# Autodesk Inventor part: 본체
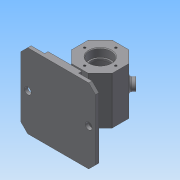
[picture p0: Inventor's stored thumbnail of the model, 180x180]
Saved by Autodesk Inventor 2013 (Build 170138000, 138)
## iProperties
Created: 2018-06
Part Number: 본체
Material: 일반
Document SubType Name: Modeling
Designer: Administrator
Density: 1 g/cm^3
Author: Administrator
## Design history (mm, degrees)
sketch "스케치1"
  geometry: L1 (-55, -62)-(55, -62); L2 (55, -62)-(55, -57); L3 (55, -57)-(25, -57); L4 (25, -57)-(25, -52); L5 (25, -52)-(-25, -52); L6 (-25, -52)-(-25, -57); L7 (-25, -57)-(-55, -57); L8 (-55, -57)-(-55, -62); L9 (0, 0)-(12.426, 30); L10 (0, 0)-(-12.426, 30); L11 (0, 0)-(0, 43.972); L12 (0, 0)-(-21.128, 0); L13 (12.426, 30)-(-12.426, 30); C1 r 30 at (0, 0); 1 further point
  constraints: 26 end point, 7 parallel, 2 perpendicular, 1 centre point, 1 coincident, 1 horizontal
  dimensions: "d0" = 60 diameter of C1; "d1" = 22.5 deg angle of L9 L11; "d3" = 22.5 deg angle of L11 L10; "d6" = 30 distance between parallel lines of L13 L12; "d7" = 92 distance from line of L1.start L13; "d8" = 110 distance of L1.start L1.end; "d9" = 55 horizontal distance of point (0, 0) L1.start; "d10" = 10 vertical distance of L4.end L1.end; "d11" = 5 distance of L3.end L4.end; "d12" = 5 distance of L5.end L6.end; "d13" = 30 distance between parallel lines of L6 L8; "d14" = 30 distance between parallel lines of L2 L4
extrude "돌출1" new body sketch "스케치1" stored distance "d15" = 110; taper "d16" = 0 deg
extrude "돌출2" join sketch "스케치1" stored distance "d17" = 70; taper "d18" = 0 deg
sketch "스케치2"
  geometry: L1 (0, 110)-(50, 110) reference; L2 (20, 74)-(20, 36); L3 (30, 36)-(30, 74); L4 (25, 55)-(6.101, 55); A1 r 5 centre (25, 36) between (20, 36) and (30, 36); A2 r 5 centre (25, 74) between (30, 74) and (20, 74)
  constraints: 6 end point, 4 point on circle, 4 tangent, 2 centre point, 2 perpendicular, 1 parallel, 1 vertical alignment
  dimensions: "d24" = 10 distance between parallel lines of L3 L2; "d26" = 38 distance of A1.centre A2.centre; "d27" = 24 dimension on A2 L4
extrude "돌출3" join sketch "스케치2" stored distance "d28" = 70; taper "d29" = 0 deg
sketch "스케치3"
  geometry: L1 (30, 110)-(30, 0) reference; C1 r 5 at (20, 55); 1 further point
  constraints: 1 centre point, 1 horizontal alignment
  dimensions: "d30" = 10 diameter of C1; "d31" = 10 distance from line of C1.centre L1
extrude "돌출4" cut sketch "스케치3" distance "d32" = 70; taper "d33" = 0 deg
sketch "스케치5"
  geometry: 1 further point
hole "구멍1" sketch "스케치5" at (0, 0) diameter "d34" = 28; stored, may be unused: countersink angle "d38" = 90 deg, drill point angle "d40" = 0 deg; dims "d35" = 6, "d36" = 32, "d37" = 12, "d39" = 15
sketch "스케치6"
  geometry: 1 further point
hole "구멍2" sketch "스케치6" at (0, 0) diameter "d41" = 28; stored, may be unused: countersink angle "d45" = 90 deg, drill point angle "d47" = 0 deg; dims "d42" = 6, "d43" = 32, "d44" = 12, "d46" = 15
hole "구멍3" diameter "d50" = 50; stored, may be unused: countersink angle "d54" = 90 deg, drill point angle "d56" = 0 deg; dims "d48" = 10, "d49" = 10, "d51" = 6, "d52" = 32, "d53" = 12, "d55" = 40
sketch "스케치7"
  geometry: C1 r 16 at (0, 0) reference; 1 further point
  constraints: 1 vertical alignment
  dimensions: "d57" = 23 distance of point (0, 23) C1.centre
hole "구멍4" sketch "스케치7" at (0, 23) diameter "d58" = 3.242; stored, may be unused: countersink angle "d62" = 90 deg, drill point angle "d64" = 118 deg; dims "d59" = 8, "d60" = 32, "d61" = 12, "d63" = 10
sketch "스케치8"
  geometry: L1 (24.853, 0)-(0, 0) reference; L2 (-17.574, 70)-(-17.574, 0) reference; 2 further points
  constraints: 1 other
  dimensions: "d68" = 30 distance from line of L2 point (12.426, 35); "d69" = 35 distance from line of L1 point (12.426, 35)
feature "엠보싱1" sketch "스케치8" dims "d70" = 0.5, "d71" = 0
node "작업 평면1"
sketch "스케치9"
  geometry: L1 (50, -62)-(50, -57) reference; L2 (50, -57)-(55, -57) reference; L3 (55, -57)-(55, -62) reference; L4 (55, -62)-(50, -62) reference; L5 (5, -30)-(5, -52) reference; L6 (5, -52)-(25, -52) reference; L7 (25, -52)-(25, -57) reference; L8 (25, -57)-(40, -57) reference; L9 (40, -57)-(40, -62) reference; L10 (40, -62)-(-40, -62) reference; L11 (-40, -62)-(-40, -57) reference; L12 (-40, -57)-(-25, -57) reference; L13 (-25, -57)-(-25, -52) reference; L14 (-25, -52)-(-5, -52) reference; L15 (-5, -52)-(-5, -30) reference; L16 (-5, -30)-(-12.426, -30) reference; L17 (-12.426, -30)-(-30, -12.426) reference; L18 (-30, -12.426)-(-30, 12.426) reference; L19 (-30, 12.426)-(-12.426, 30) reference; L20 (-12.426, 30)-(-2.862, 30) reference; L21 (-2.862, 30)-(-2.862, 30.5) reference; L22 (-2.862, 30.5)-(-2.365, 30.5) reference; L23 (-2.365, 30.5)-(-2.365, 30) reference; L24 (-2.365, 30)-(12.426, 30) reference; L25 (12.426, 30)-(30, 12.426) reference; L26 (30, 12.426)-(30, -12.426) reference; L27 (30, -12.426)-(12.426, -30) reference; L28 (12.426, -30)-(5, -30) reference; L29 (-55, -62)-(-55, -57) reference; L30 (-55, -57)-(-50, -57) reference; L31 (-50, -57)-(-50, -62) reference; L32 (-50, -62)-(-55, -62) reference; L33 (0, 0)-(26.163, 26.163); C1 r 25 at (0, 0) reference; 1 further point
  constraints: 2 end point, 1 parallel
  dimensions: "d73" = 37 distance of L33.start L33.end
  node "절단 모서리 투영1"
node "작업 평면2"
sketch "스케치10"
  geometry: C1 r 8 at (0, 0); 1 further point
  constraints: 1 centre point, 1 coincident
  dimensions: "d74" = 16 diameter of C1
extrude "돌출5" join sketch "스케치10" stored distance "d75" = 70; taper "d76" = 0 deg
hole "구멍5" diameter "d79" = 8; stored, may be unused: countersink angle "d83" = 90 deg, drill point angle "d85" = 0 deg; dims "d77" = 10, "d78" = 10, "d80" = 8, "d81" = 32, "d82" = 12, "d84" = 10
chamfer "모따기1" distance "d86" = 10; stored, may be unused: second distance "d87" = 2, angle "d88" = 45 deg
chamfer "모따기2" distance "d89" = 1; stored, may be unused: second distance "d90" = 2, angle "d91" = 45 deg
fillet "모깎기1" dims "d92" = 1, "d93" = 2, "d94" = 3, "d95" = 0.3
node "솔리드1"
pattern_circular "원형 패턴1" dims angle "d20" = 360 deg
mirror "대칭1"
pattern_circular "원형 패턴2" dims angle "d66" = 360 deg
mirror "대칭2"
other parameters: "d72" = 0
